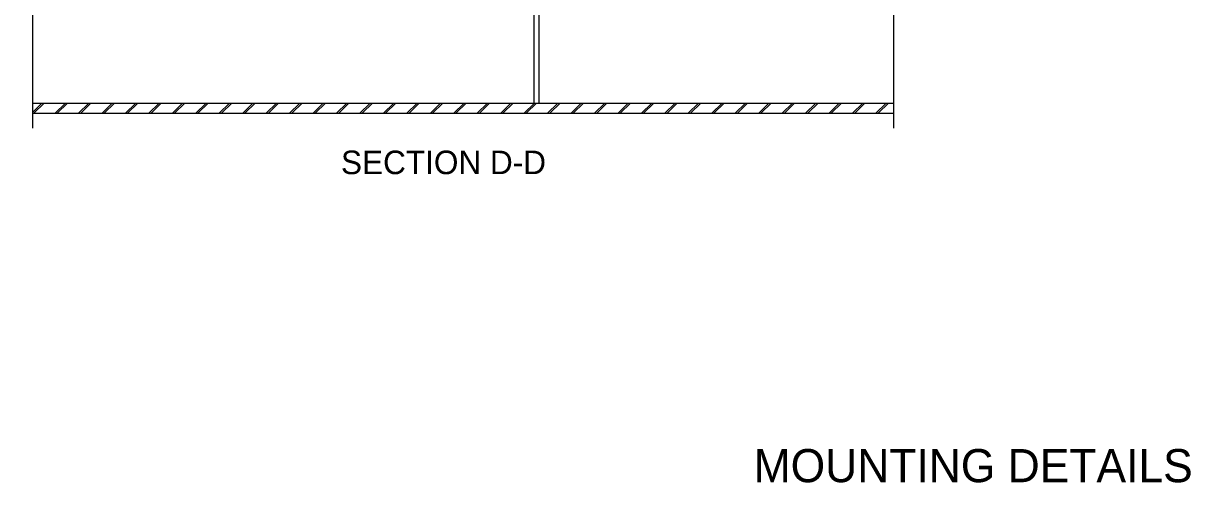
# Model space of a CAD drawing. Extents: x 927736.2 to 927809.6, y 636703.6 to 636757.7.
# Drawn here: x 927786.14 to 927809.58, y 636705.98 to 636715.22 of the extents above; entities that cross this region are included whole.
import ezdxf

# ---------------------------------------------------------------- set-up
doc = ezdxf.new("R2010")
doc.units = 0
for name, color, linetype in [('Default', 7, 'Continuous'), ('DimLines_dp', 7, 'Continuous'), ('Miscellaneous3', 7, 'Continuous'), ('TextMisc', 7, 'Continuous')]:
    doc.layers.add(name, color=color, linetype=linetype)

msp = doc.modelspace()

# ---------------------------------------------------------------- linework, layer by layer
at = {"layer": 'DimLines_dp'}
for points in [[(927786.333, 636713.104), (927786.333, 636722.378), (927786.142, 636722.378), (927786.333, 636722.461), (927786.524, 636722.544), (927786.333, 636722.544), (927786.333, 636731.807)], [(927803.622, 636713.104), (927803.622, 636722.378), (927803.431, 636722.378), (927803.622, 636722.461), (927803.813, 636722.544), (927803.622, 636722.544), (927803.622, 636724.526)]]:
    msp.add_lwpolyline(points, dxfattribs=at)
at = {"layer": 'Miscellaneous3'}
for p, q in [((927796.389, 636715.462), (927796.389, 636713.612)), ((927796.492, 636715.462), (927796.492, 636713.612)), ((927786.333, 636713.612), (927803.622, 636713.612)), ((927786.333, 636713.431), (927786.514, 636713.612)), ((927786.352, 636713.407), (927786.557, 636713.612)), ((927786.779, 636713.407), (927786.985, 636713.612)), ((927786.823, 636713.407), (927787.028, 636713.612)), ((927787.25, 636713.407), (927787.456, 636713.612)), ((927787.294, 636713.407), (927787.499, 636713.612)), ((927787.721, 636713.407), (927787.926, 636713.612)), ((927787.765, 636713.407), (927787.97, 636713.612)), ((927788.192, 636713.407), (927788.397, 636713.612)), ((927788.236, 636713.407), (927788.441, 636713.612)), ((927788.663, 636713.407), (927788.868, 636713.612)), ((927788.707, 636713.407), (927788.912, 636713.612)), ((927789.134, 636713.407), (927789.339, 636713.612)), ((927789.177, 636713.407), (927789.383, 636713.612)), ((927789.605, 636713.407), (927789.81, 636713.612)), ((927789.648, 636713.407), (927789.854, 636713.612)), ((927790.076, 636713.407), (927790.281, 636713.612)), ((927790.119, 636713.407), (927790.325, 636713.612)), ((927790.547, 636713.407), (927790.752, 636713.612)), ((927790.59, 636713.407), (927790.796, 636713.612)), ((927791.018, 636713.407), (927791.223, 636713.612)), ((927791.061, 636713.407), (927791.267, 636713.612)), ((927791.489, 636713.407), (927791.694, 636713.612)), ((927791.532, 636713.407), (927791.738, 636713.612)), ((927791.959, 636713.407), (927792.165, 636713.612)), ((927792.003, 636713.407), (927792.208, 636713.612)), ((927792.43, 636713.407), (927792.636, 636713.612)), ((927792.474, 636713.407), (927792.679, 636713.612)), ((927792.901, 636713.407), (927793.107, 636713.612)), ((927792.945, 636713.407), (927793.15, 636713.612)), ((927793.372, 636713.407), (927793.578, 636713.612)), ((927793.416, 636713.407), (927793.621, 636713.612)), ((927793.843, 636713.407), (927794.049, 636713.612)), ((927793.887, 636713.407), (927794.092, 636713.612)), ((927794.314, 636713.407), (927794.52, 636713.612)), ((927794.358, 636713.407), (927794.563, 636713.612)), ((927794.785, 636713.407), (927794.99, 636713.612)), ((927794.829, 636713.407), (927795.034, 636713.612)), ((927795.256, 636713.407), (927795.461, 636713.612)), ((927795.3, 636713.407), (927795.505, 636713.612)), ((927795.727, 636713.407), (927795.932, 636713.612)), ((927795.771, 636713.407), (927795.976, 636713.612)), ((927796.198, 636713.407), (927796.403, 636713.612)), ((927796.241, 636713.407), (927796.447, 636713.612)), ((927796.669, 636713.407), (927796.874, 636713.612)), ((927796.712, 636713.407), (927796.918, 636713.612)), ((927797.14, 636713.407), (927797.345, 636713.612)), ((927797.183, 636713.407), (927797.389, 636713.612)), ((927797.611, 636713.407), (927797.816, 636713.612)), ((927797.654, 636713.407), (927797.86, 636713.612)), ((927798.082, 636713.407), (927798.287, 636713.612)), ((927798.125, 636713.407), (927798.331, 636713.612)), ((927798.553, 636713.407), (927798.758, 636713.612)), ((927798.596, 636713.407), (927798.802, 636713.612)), ((927799.023, 636713.407), (927799.229, 636713.612)), ((927799.067, 636713.407), (927799.272, 636713.612)), ((927799.494, 636713.407), (927799.7, 636713.612)), ((927799.538, 636713.407), (927799.743, 636713.612)), ((927799.965, 636713.407), (927800.171, 636713.612)), ((927800.009, 636713.407), (927800.214, 636713.612)), ((927800.436, 636713.407), (927800.642, 636713.612)), ((927800.48, 636713.407), (927800.685, 636713.612)), ((927800.907, 636713.407), (927801.113, 636713.612)), ((927800.951, 636713.407), (927801.156, 636713.612)), ((927801.378, 636713.407), (927801.584, 636713.612)), ((927801.422, 636713.407), (927801.627, 636713.612)), ((927801.849, 636713.407), (927802.055, 636713.612)), ((927801.893, 636713.407), (927802.098, 636713.612)), ((927802.32, 636713.407), (927802.525, 636713.612)), ((927802.364, 636713.407), (927802.569, 636713.612)), ((927802.791, 636713.407), (927802.996, 636713.612)), ((927802.835, 636713.407), (927803.04, 636713.612)), ((927803.262, 636713.407), (927803.467, 636713.612)), ((927803.306, 636713.407), (927803.511, 636713.612)), ((927786.333, 636713.407), (927803.622, 636713.407))]:
    msp.add_line(p, q, dxfattribs=at)

# ---------------------------------------------------------------- texts
at = {"layer": 'Default'}
msp.add_text('SECTION D-D', height=0.4736, dxfattribs=at).set_placement((927792.52, 636712.182))
at = {"layer": 'TextMisc'}
msp.add_text('       MOUNTING DETAILS        ', height=0.66664, dxfattribs=at).set_placement((927799.072, 636705.988))

doc.saveas('drawing.dxf')
